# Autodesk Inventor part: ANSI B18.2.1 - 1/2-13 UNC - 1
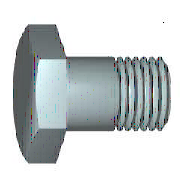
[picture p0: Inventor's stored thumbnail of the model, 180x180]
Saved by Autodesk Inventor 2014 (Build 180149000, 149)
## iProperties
IsCustomPart: 0
Created: 2008-02
Part Number: ANSI B18.2.1 - 1/2-13 UNC - 1
Material: Steel, Mild
Description: Hex Cap Screw
Document SubType Name: Modeling
Standard: ANSI B18.2.1
Designer: floress
Standard Revision: 1996
Standards Organization: ANSI
Language: en-US
Size Designation: 1/2-13 UNC - 1
Categories: <MemberInstance><Categories><Category DisplayName="Fasteners" InternalName="e4da775c-781d-43d5-af7c-5136215cf5a6" Mnemonic="FSTN"><Category DisplayName="Bolts"
Density: 7.86 g/cm^3
Mass: 44.2513 g
Surface Area: 21.0371 cm^2
Volume: 5.62994 cm^3
Appearance: Steel
Author: floress
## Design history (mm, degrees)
sketch "Sketch1"
  geometry: L1 (0, 8.572)-(0, 6.35); L2 (4.877, 6.35)-(25.4, 6.35); L3 (25.4, 6.35)-(25.4, 0); L4 (25.4, 0)-(-0.635, 0); L5 (-5.842, 0)-(30.607, 0) reference; L6 (-0.635, 0)-(-0.635, 8.572); L7 (-0.635, 8.572)-(0, 8.572); L8 (4.877, 6.35)-(0.002, 6.35); L9 (0.002, 6.35)-(0, 6.35); L10 (0, -1.715)-(0, 10.287) reference
  constraints: 16 end point, 2 collinear, 2 perpendicular, 1 parallel
  dimensions: "d0" = 25.4 distance between parallel lines of L3 L1 (= NLG); "d1" = 20.5232 distance from line of L2.start L3 (= GEL); "d2" = 12.7 diameter of L2 L4 (= GD); "d9" = 0.6351 distance between parallel lines of L6 L1 (computed from SD); "d10" = 17.145 diameter of L7 L4 (= SD2); "d13" = 4.87436 distance of L2.start L8.end (computed from GAL); "d14" = 12.7 diameter of L9 L4 (= BDM)
revolve "Body" sketch "Sketch1" stored, may be unused: angle "d12" = 90 deg
sketch "Sketch2"
  geometry: L1 (0, 10.999)-(9.525, 5.499); L2 (9.525, 5.499)-(9.525, -5.499); L3 (9.525, -5.499)-(0, -10.999); L4 (0, -10.999)-(-9.525, -5.499); L5 (-9.525, -5.499)-(-9.525, 5.499); L6 (-9.525, 5.499)-(0, 10.999); 2 further points
  constraints: 12 end point, 1 coincident, 1 vertical, 11 other
  dimensions: "d11" = 19.05 distance between parallel lines of L5 L2 (= SW)
extrude "Head" join sketch "Sketch2" distance "d3" = 7.3025 (= KOH - SD); taper "d4" = 0 deg
sketch "Sketch4"
  geometry: L1 (-7.938, 9.525)-(-7.938, 10.999); L2 (-7.938, 10.999)-(-7.087, 10.999); L3 (-7.087, 10.999)-(-7.938, 9.525); L4 (-9.398, 0)-(0.825, 0) reference; L5 (-0.635, 10.999)-(-7.938, 10.999) reference; L6 (-7.938, 5.499)-(-7.938, 10.999) reference
  constraints: 6 end point, 2 collinear, 1 perpendicular, 1 vertical
  dimensions: "d5" = 30 deg angle of L3 L1 (= ANG1); "d19" = 19.05 diameter of L1.start L4 (= SW0)
revolve "Chamfer1" sketch "Sketch4" stored, may be unused: angle "d21" = 90 deg
workplane "Work Plane1"
fillet "Fillet2" dims "d63" = 0.635 (= R)
body "Solid1"
feature "Thread" dims "d15" = 20.5232 (= GEL), "d16" = 0
chamfer "Chamfer2" distance "d6" = 1.16332 (= -0.5 x SPD + 0.5 x GD); stored, may be unused: second distance "d7" = 1.16342 (computed from GUL), angle "d55" = 45 deg
other parameters: "NLG" = 25.4 [user parameter; used in 2 equation terms], "GD" = 12.7 (= NND) [user parameter; used in 2 equation terms], "BDM" = 12.7 [user parameter; used in 1 equation term], "KOH" = 7.9375 [user parameter; used in 1 equation term], "GEL" = 20.5232 [user parameter; used in 2 equation terms], "SW" = 19.05 [user parameter; used in 3 equation terms], "SW0" = 19.05 (= SW) [user parameter; used in 1 equation term], "SPD" = 10.37336 (= GD1) [user parameter; used in 1 equation term], "SD2" = 17.145 [user parameter; used in 1 equation term], "SD" = 0.635 [user parameter; used in 3 equation terms], "ANG1" = 30 deg [user parameter; used in 1 equation term], "GAL" = 4.87426 [user parameter; used in 1 equation term], "GUL" = 1.16332 [user parameter; used in 2 equation terms], "d8" = 0, "R" = 0.635 [user parameter; used in 1 equation term], "d58" = 0, "d62" = -24.87168 (= -NLG - SD + GUL), "THREADDIA" = 12.7 [user parameter], "TOA" = 30 deg [user parameter], "RR" = 0.762 [user parameter], "PTC" = 1.95385 (computed from TPU) [user parameter], "NND" = 12.7 [user parameter; used in 1 equation term], "E0" = 22.00275 (= 1.155 x SW) [user parameter], "SLG" = 0 [user parameter], "GD1" = 10.37336 [user parameter; used in 1 equation term]
